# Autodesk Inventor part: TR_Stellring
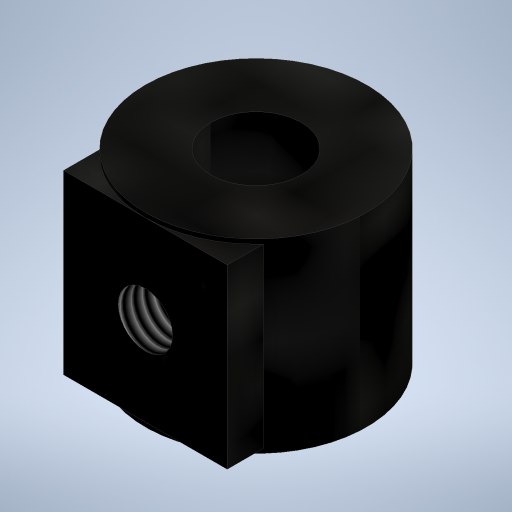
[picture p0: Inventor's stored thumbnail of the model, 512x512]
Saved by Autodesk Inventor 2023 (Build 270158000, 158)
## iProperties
Created: 2023-11
Part Number: TR_Stellring
Material: PC/ABS-Kunststoff
Document SubType Name: Modeling
Designer: Administrator
Density: 0.357273 g/cm^3
Appearance: Glatt - Schwarz
Author: Administrator
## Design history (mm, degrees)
sketch "Skizze1"
  geometry: C1 r 5 at (0, 0); 1 further point
  constraints: 1 centre point, 1 coincident
  dimensions: "d0" = 10 diameter of C1 (= Einheitsmaß)
extrude "Extrusion1" new body sketch "Skizze1" distance "d1" = 8.4; taper "d2" = 0 deg
sketch "Skizze2"
  geometry: L1 (-3.7, 8.2)-(3.7, 8.2); L2 (3.7, 8.2)-(3.7, 0.2); L3 (3.7, 0.2)-(-3.7, 0.2); L4 (-3.7, 0.2)-(-3.7, 8.2); L5 (-5, 0)-(-5, 8.4) reference; 4 further points
  constraints: 8 end point, 3 midpoint, 2 parallel, 1 horizontal, 1 horizontal alignment, 1 perpendicular, 1 vertical alignment
  dimensions: "d3" = 7.4 distance of L2.end L3.end; "d4" = 8 distance of L1.end L2.end
extrude "Extrusion2" join sketch "Skizze2" distance "d5" = 5; taper "d6" = 0 deg
sketch "Skizze3"
  geometry: L1 (-3.7, 8.2)-(-3.7, 0.2) reference; 3 further points
  constraints: 1 horizontal alignment, 1 midpoint, 1 vertical alignment
hole "Bohrung1" sketch "Skizze3" at (0, 4.2) diameter "d7" = 2.459; stored, may be unused: countersink angle "d11" = 90 deg, drill point angle "d13" = 0 deg; dims "d8" = 5, "d9" = 4, "d10" = 2, "d12" = 5
sketch "Skizze5"
  geometry: C1 r 2.05 at (0, 0); 1 further point
  constraints: 1 centre point, 1 coincident
  dimensions: "d17" = 4.1 diameter of C1 (= DAchsAufnahme)
extrude "Extrusion4" cut sketch "Skizze5" extent not by distance; stored distance "d18" = 0; taper "d19" = 0 deg
node "Volumenkörper1"
other parameters: "Einheitsmaß" = 10 [user parameter; used in 1 equation term], "Radius" = 2.075 [user parameter], "Fasen" = 0.5 [user parameter], "Dicke" = 0.8 [user parameter], "Breitloch" = 2 [user parameter], "Langloch" = 32 [user parameter], "AchteckUmkreis" = 6 [user parameter], "DAchsAufnahme" = 4.1 [user parameter; used in 1 equation term], "AchsDurchmesser" = 4 [user parameter], "AchsFase" = 0.5 [user parameter]
